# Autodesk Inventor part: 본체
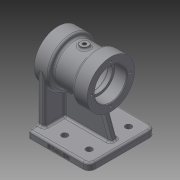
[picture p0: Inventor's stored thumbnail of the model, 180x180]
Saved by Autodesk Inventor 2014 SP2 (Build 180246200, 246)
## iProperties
Created: 2020-06
Part Number: 본체
Material: Generic
Document SubType Name: Modeling
Designer: Administrator
Density: 1 g/cm^3
Appearance: Default
Author: Administrator
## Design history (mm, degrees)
sketch "스케치1"
  geometry: L1 (-39, 0)-(39, 0); L2 (-39, 23.5)-(-21, 23.5); L3 (-21, 23.5)-(-21, 20); L4 (-21, 20)-(-15, 20); L5 (-15, 20)-(-15, 23); L6 (-15, 23)-(15, 23); L7 (15, 23)-(15, 20); L8 (15, 20)-(21, 20); L9 (21, 20)-(21, 23.5); L10 (21, 23.5)-(39, 23.5); L11 (39, 23.5)-(39, 35); L12 (39, 35)-(17, 35); L13 (17, 35)-(17, 29); L14 (17, 29)-(-17, 29); L15 (-17, 29)-(-17, 35); L16 (-17, 35)-(-39, 35); L17 (-39, 35)-(-39, 23.5); 2 further points
  constraints: 34 end point, 10 parallel, 5 perpendicular, 2 vertical alignment, 1 coincident, 1 collinear, 1 horizontal, 1 midpoint
  dimensions: "d0" = 78 distance of L1.start L1.end; "d1" = 47 diameter of L2 L1; "d2" = 40 diameter of L4 L1; "d3" = 70 diameter of L16 L1; "d4" = 22 distance of L15.end L16.end; "d5" = 22 distance of L11.end L12.end; "d6" = 47 diameter of L10 L1; "d7" = 40 diameter of L8 L1; "d8" = 70 diameter of L12 L1; "d9" = 18 distance of L2.start L2.end; "d10" = 6 distance of L3.end L4.end; "d11" = 30 distance of L5.end L6.end; "d12" = 18 distance of L9.end L10.end; "d13" = 46 diameter of L6 L1; "d14" = 58 diameter of L14 L1
revolve "회전1" sketch "스케치1" stored, may be unused: angle "d15" = 90 deg
node "작업 평면1"
sketch "스케치2"
  geometry: L1 (-34, 49)-(56, 49); L2 (56, 49)-(56, -49); L3 (56, -49)-(-34, -49); L4 (-34, -49)-(-34, 49); L5 (-34, 49)-(36, 49); L6 (36, 49)-(36, 29); L7 (36, 29)-(0, 29); L8 (0, 29)-(0, -29); L9 (0, -29)-(36, -29); L10 (36, -29)-(36, 29); L11 (-39, -35)-(-39, 35) reference; C1 r 4.5 at (36, 29); C2 r 4.5 at (0, 29); C3 r 4.5 at (0, -29); C4 r 4.5 at (36, -29); 2 further points
  constraints: 20 end point, 5 perpendicular, 4 centre point, 4 coincident, 3 parallel, 1 horizontal, 1 horizontal alignment, 1 midpoint, 1 point on line
  dimensions: "d20" = 20 distance of L5.end L6.end; "d21" = 9 diameter of C1; "d22" = 36 distance of L7.start L7.end; "d23" = 58 distance of L7.end L8.end; "d24" = 9 diameter of C2; "d25" = 9 diameter of C3; "d26" = 9 diameter of C4; "d39" = 5 distance between parallel lines of L4 L11; "d40" = 90 distance of L1.start L1.end; "d41" = 70 distance from line of L6.end L4; "d42" = 98 distance of L1.end L2.end
extrude "돌출1" join sketch "스케치2" distance "d27" = 10; taper "d28" = 0 deg
sketch "스케치3"
  geometry: L1 (-34, 49)-(-34, -49) reference; L2 (-34, 0)-(44, 0); L3 (-34, 35)-(-24, 35); L4 (-34, -35)-(-24, -35); L5 (-34, 35)-(-34, -35); L6 (-24, 35)-(-24, -35); 1 further point
  constraints: 10 end point, 1 midpoint, 1 parallel, 1 perpendicular, 1 vertical, 1 vertical alignment
  dimensions: "d31" = 10 distance of L3.start L3.end; "d33" = 10 distance of L4.start L4.end; "d35" = 70 distance of L3.start L4.start
node "작업 평면2"
extrude "돌출2" join sketch "스케치3" stored distance "d51" = 10; taper "d52" = 0 deg
node "작업 평면3"
sketch "스케치5"
  geometry: L1 (-39, -22.962)-(-21, -22.962) reference; L2 (-21, -22.962)-(-21, -19.365) reference; L3 (-21, -19.365)-(-15, -19.365) reference; L4 (-15, -19.365)-(-15, -22.45) reference; L5 (-15, -22.45)-(15, -22.45) reference; L6 (15, -22.45)-(15, -19.365) reference; L7 (15, -19.365)-(21, -19.365) reference; L8 (21, -19.365)-(21, -22.962) reference; L9 (21, -22.962)-(39, -22.962) reference; L10 (39, -22.962)-(39, -34.641) reference; L11 (39, -34.641)-(17, -34.641) reference; L12 (17, -34.641)-(17, -28.566) reference; L13 (17, -28.566)-(-17, -28.566) reference; L14 (-17, -28.566)-(-17, -34.641) reference; L15 (-17, -34.641)-(-24, -34.641) reference; L16 (-24, -34.641)-(-24, -70) reference; L17 (-24, -70)-(56, -70) reference; L18 (56, -70)-(56, -80) reference; L19 (56, -80)-(-34, -80) reference; L20 (-34, -80)-(-34, -34.641) reference; L21 (-34, -34.641)-(-39, -34.641) reference; L22 (-39, -34.641)-(-39, -22.962) reference; L23 (-21, 22.962)-(-39, 22.962) reference; L24 (-39, 22.962)-(-39, 34.641) reference; L25 (-39, 34.641)-(-17, 34.641) reference; L26 (-17, 34.641)-(-17, 28.566) reference; L27 (-17, 28.566)-(17, 28.566) reference; L28 (17, 28.566)-(17, 34.641) reference; L29 (17, 34.641)-(39, 34.641) reference; L30 (39, 34.641)-(39, 22.962) reference; L31 (39, 22.962)-(21, 22.962) reference; L32 (21, 22.962)-(21, 19.365) reference; L33 (21, 19.365)-(15, 19.365) reference; L34 (15, 19.365)-(15, 22.45) reference; L35 (15, 22.45)-(-15, 22.45) reference; L36 (-15, 22.45)-(-15, 19.365) reference; L37 (-15, 19.365)-(-21, 19.365) reference; L38 (-21, 19.365)-(-21, 22.962) reference; L39 (56, -70)-(44, -70); L40 (44, -70)-(31.13, -34.641); L41 (31.13, -34.641)-(17, -34.641); L42 (17, -28.566)-(-17, -28.566); L43 (-17, -34.641)-(-24, -34.641); L44 (-24, -70)-(-24, -34.641); L45 (-17, -34.641)-(-17, -28.566); L46 (17, -28.566)-(17, -34.641); L47 (-24, -70)-(44, -70); 1 further point
  constraints: 18 end point, 6 collinear, 2 point on line, 1 parallel
  dimensions: "d54" = 12 distance of L17.end L39.end; "d55" = 110 deg angle of L39 L40
extrude "돌출3" join sketch "스케치5" distance "d56" = 10; taper "d57" = 0 deg
node "작업 평면4"
sketch "스케치7" dims "d61" = 57
  geometry: L1 (0, 0)-(0, 28.5); C1 r 23.5 at (0, 0) reference
  constraints: 2 end point, 1 coincident, 1 vertical, 1 vertical alignment, 2 other
hole "구멍1" sketch "스케치7" at (0, 28.5) diameter "d62" = 3.242; stored, may be unused: countersink angle "d66" = 90 deg, drill point angle "d68" = 118 deg; dims "d63" = 10, "d64" = 4, "d65" = 2, "d67" = 12
fillet "모깎기1" dims "d79" = 3
chamfer "모따기1" distance "d80" = 1; stored, may be unused: second distance "d81" = 2, angle "d82" = 45 deg
fillet "모깎기2" dims "d83" = 3, "d84" = 0.3
sketch "스케치11"
  geometry: L1 (0, 0)-(0, 7) reference; L2 (0, 0)-(90, 0) reference; 2 further points
  constraints: 1 other
  dimensions: "d93" = 45 distance from line of point (45, 4) L1; "d94" = 4 distance from line of L2 point (45, 4)
feature "엠보싱1" sketch "스케치11" dims "d95" = 0.5, "d96" = 0
node "작업 평면6"
sketch "스케치12"
  geometry: C1 r 6 at (0, 0); 1 further point
  constraints: 1 centre point, 1 coincident
  dimensions: "d98" = 12 diameter of C1
extrude "돌출5" join sketch "스케치12" stored distance "d99" = 3; taper "d100" = 0 deg
fillet "모깎기3" dims "d101" = 3
sketch "스케치13"
  geometry: A1 r 6 centre (0, 0) between (6, 0) and (-6, 0) reference
hole "구멍4" sketch "스케치13" at (0, 0) diameter "d102" = 5.188; stored, may be unused: countersink angle "d106" = 90 deg, drill point angle "d108" = 0 deg; dims "d103" = 10, "d104" = 4, "d105" = 2, "d107" = 12
fillet "모깎기4" dims "d109" = 9
fillet "모깎기5" dims "d110" = 3
fillet "모깎기6" dims "d111" = 3
fillet "모깎기7" dims "d112" = 3
fillet "모깎기8" dims "d113" = 3
fillet "모깎기9" dims "d114" = 3
node "솔리드1"
pattern_circular "원형 패턴1" dims angle "d70" = 360 deg
mirror "대칭1"
node "절단 모서리 투영1"
other parameters: "d44" = 5, "d53" = 5, "d97" = 32
